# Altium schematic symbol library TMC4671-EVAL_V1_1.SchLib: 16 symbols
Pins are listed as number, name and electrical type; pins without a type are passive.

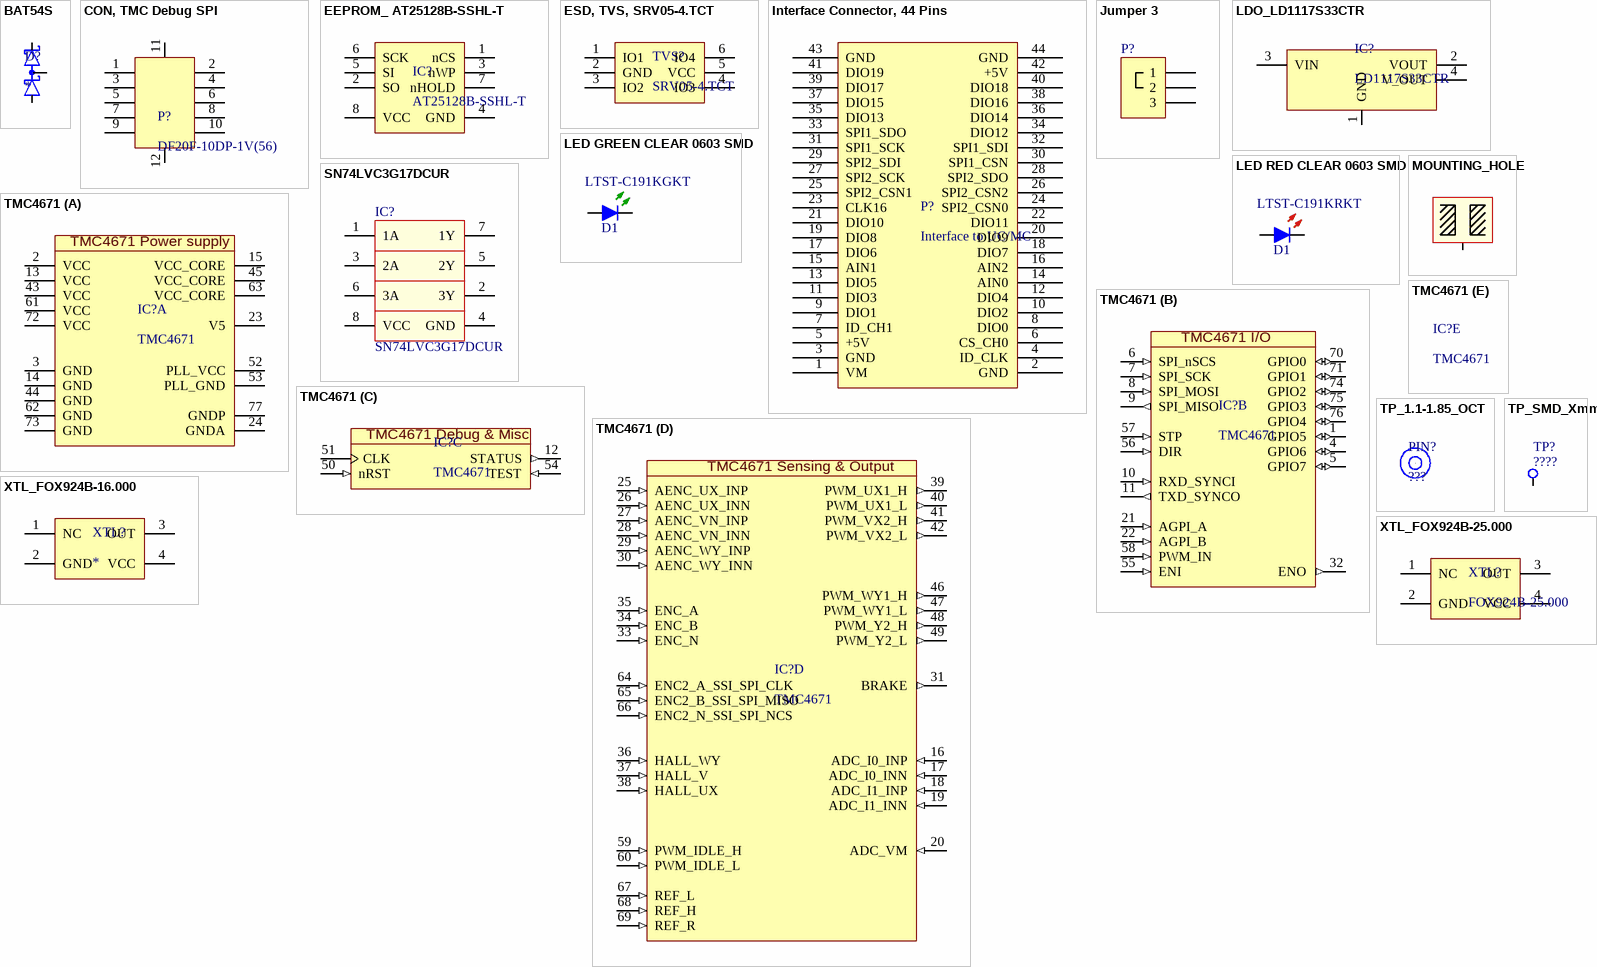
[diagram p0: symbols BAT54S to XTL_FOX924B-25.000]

## BAT54S
designator D?
Small Signal Schottky Diode, Dual Series, 30 V, 200 mA, 1 V, 600 mA, 125 °C; MPN: BAT54S; MF: TAIWAN SEMICONDUCTOR
footprint SOT95P237X130-3N (SOT23, 3-Leads, Body 2,90x2,37mm, Pitch 0,95mm, IPC Medium Density)
pins: 1 A1, 2 C2, 3 C1A2

## CON, TMC Debug SPI
designator P?, comment DF20F-10DP-1V(56)
Wire-To-Board Connector, 1 mm, 10 Contacts, Header, DF20 Series, Surface Mount, 2 Rows; MF: Hirose Electric Co Ltd
footprint CON, TMC Debug SPI (Footprint not found)
pins: 1, 2, 3, 4, 5, 6, 7, 8, 9, 10, 11, 12

## EEPROM_ AT25128B-SSHL-T
designator IC?, comment AT25128B-SSHL-T
EEPROM, SPI, 128 Kbit, 16K x 8bit, 20 MHz, SOIC, 8 Pins; MF: MICROCHIP
footprint SOP127P600X175-8N (SOP, 8-Leads, Body 4,92x3,90mm, Pitch 1,27mm, IPC Medium Density)
pins: 1 nCS, 2 SO, 3 nWP, 4 GND, 5 SI, 6 SCK, 7 nHOLD, 8 VCC

## ESD, TVS, SRV05-4.TCT
designator TVS?, comment SRV05-4.TCT
ESD Protection Device, TVS, 17.5 V, SOT-23, 6 Pins, 5 V, 300 W; MF: SEMTECH
footprint SOT95P280X145-6N (SOT23, 6-Leads, Body 2,95x2,80mm, Pitch 0,95mm, IPC Medium Density)
pins: 1 IO1, 2 GND, 3 IO2, 4 IO3, 5 VCC, 6 IO4

## Interface Connector, 44 Pins
designator P?, comment Interface to UC/MC
Board-To-Board Connector, 2.54 mm, 44 Contacts, Receptacle, HLE Series, Surface Mount, 2 Rows; MPN: HLE-122-02-L-DV; MF: SAMTEC
footprint Interface_Connector
pins: 1 VM, 2 GND, 3 GND, 4 ID_CLK, 5 +5V, 6 CS_CH0, 7 ID_CH1, 8 DIO0, 9 DIO1, 10 DIO2, 11 DIO3, 12 DIO4, 13 DIO5, 14 AIN0, 15 AIN1, 16 AIN2, 17 DIO6, 18 DIO7, 19 DIO8, 20 DIO9, 21 DIO10, 22 DIO11, 23 CLK16, 24 SPI2_CSN0, 25 SPI2_CSN1, 26 SPI2_CSN2, 27 SPI2_SCK, 28 SPI2_SDO, 29 SPI2_SDI, 30 SPI1_CSN, 31 SPI1_SCK, 32 SPI1_SDI, 33 SPI1_SDO, 34 DIO12, 35 DIO13, 36 DIO14, 37 DIO15, 38 DIO16, 39 DIO17, 40 DIO18, 41 DIO19, 42 +5V, 43 GND, 44 GND

## Jumper 3
designator P?  (no BOM)
Jumper, 3-Pin
footprint TH_JMP_1X3
pins: 1, 2, 3

## LDO_LD1117S33CTR
designator IC?, comment LD1117S33CTR
Fixed LDO Voltage Regulator, 4.75V to 15V, 1.1V Dropout, 3.3Vout, 950mAout, SOT-223-4; MF: STMICROELECTRONICS
footprint SOT230P700X180-4N (SOT223, 4-Leads, Body 6,50x7,00mm (avg), Pitch 2,30mm, IPC Medium Density)
pins: 1 GND, 2 VOUT, 3 VIN, 4 V_OUT

## LED GREEN CLEAR 0603 SMD
designator D1, comment LTST-C191KGKT
Green 571nm LED Indication - Discrete 2V 0603 (1608 Metric); MF: Lite-On; Current rating: 20mA
footprint LED_0603
pins: 1 A, 2 K

## LED RED CLEAR 0603 SMD
designator D1, comment LTST-C191KRKT
Green 631nm LED Indication - Discrete 2V 0603 (1608 Metric); MF: Lite-On; Current rating: 20mA; Colour: Red
footprint LED_0603
pins: 1 A, 2 K

## MOUNTING_HOLE
designator MNT?  (value not drawn)  (no BOM)
footprint MNT_HOLE_6.35-3.2
pins: 1

## SN74LVC3G17DCUR
designator IC?
Triple Schmitt-Trigger Buffer, 74LVC3G17, 1.65 V to 5.5 V, VSSOP-8; MF: TEXAS INSTRUMENTS
footprint TSSOP50P310X90-8L (TSSOP, 8-Leads, Body 2,00x2,30mm, Pitch 0,50mm, IPC High Density)
pins: 1 1A (power), 2 3Y (power), 3 2A (power), 4 GND (power), 5 2Y (power), 6 3A (power), 7 1Y (power), 8 VCC (power)

## TMC4671
designator IC?
MF: TRINAMIC
footprint QFN40P1050X650X90_HS-77N (QFN, 76-Leads, Body 10,50x6,50mm, Pitch 0,40mm, Thermal Pad 9,00x5,00mm, IPC Medium Density)
part A pins: 2 VCC (power), 3 GND (power), 13 VCC (power), 14 GND (power), 15 VCC_CORE (power), 23 V5 (power), 24 GNDA (power), 43 VCC (power), 44 GND (power), 45 VCC_CORE (power), 52 PLL_VCC (power), 53 PLL_GND (power), 61 VCC (power), 62 GND (power), 63 VCC_CORE (power), 72 VCC (power), 73 GND (power), 77 GNDP (power)
part B pins: 1 GPIO5 (io), 4 GPIO6 (io), 5 GPIO7 (io), 6 SPI_nSCS (in), 7 SPI_SCK (in), 8 SPI_MOSI (in), 9 SPI_MISO (out), 10 RXD_SYNCI (in), 11 TXD_SYNCO (out), 21 AGPI_A (in), 22 AGPI_B (in), 32 ENO (out), 55 ENI (in), 56 DIR (in), 57 STP (in), 58 PWM_IN (in), 70 GPIO0 (io), 71 GPIO1 (io), 74 GPIO2 (io), 75 GPIO3 (io), 76 GPIO4 (io)
part C pins: 12 STATUS (out), 50 nRST (in), 51 CLK, 54 TEST (in)
part D pins: 16 ADC_I0_INP (in), 17 ADC_I0_INN (in), 18 ADC_I1_INP (in), 19 ADC_I1_INN (in), 20 ADC_VM (in), 25 AENC_UX_INP (in), 26 AENC_UX_INN (in), 27 AENC_VN_INP (in), 28 AENC_VN_INN (in), 29 AENC_WY_INP (in), 30 AENC_WY_INN (in), 31 BRAKE (out), 33 ENC_N (in), 34 ENC_B (in), 35 ENC_A (in), 36 HALL_WY (in), 37 HALL_V (in), 38 HALL_UX (in), 39 PWM_UX1_H (out), 40 PWM_UX1_L (out), 41 PWM_VX2_H (out), 42 PWM_VX2_L (out), 46 PWM_WY1_H (out), 47 PWM_WY1_L (out), 48 PWM_Y2_H (out), 49 PWM_Y2_L (out), 59 PWM_IDLE_H (in), 60 PWM_IDLE_L (in), 64 ENC2_A_SSI_SPI_CLK (in), 65 ENC2_B_SSI_SPI_MISO (in), 66 ENC2_N_SSI_SPI_NCS (in), 67 REF_L (in), 68 REF_H (in), 69 REF_R (in)

## TP_1.1-1.85_OCT
designator PIN?, comment ???  (no BOM)
TH testpoint, 1.1 hole, 1.85 pad, octagonal
footprint TP_1.1-1.85_OCT
pins: 1 (power)

## TP_SMD_Xmm
designator TP?, comment ????  (no BOM)
SMD testpoint, 1.2mm pad, round
footprint TP_SMD_1.2MM_ROUND
pins: 1

## XTL_FOX924B-16.000
designator XTL?
TCXO, 16 MHz, 2.5 ppm, SMD, 5mm x 3.2mm, HCMOS, 3.3 V, FOX924 Series; MPN: FOX924B-16.000; MF: FOX ELECTRONICS
footprint XTL_FOX924B-16.000
pins: 1 NC, 2 GND, 3 OUT, 4 VCC

## XTL_FOX924B-25.000
designator XTL?, comment FOX924B-25.000
TCXO, 25 MHz, 2.5 ppm, SMD, 5mm x 3.2mm, HCMOS, 3.3 V, FOX924 Series; MF: FOX ELECTRONICS
footprint XTL_FOX924B-16.000
pins: 1 NC, 2 GND, 3 OUT, 4 VCC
